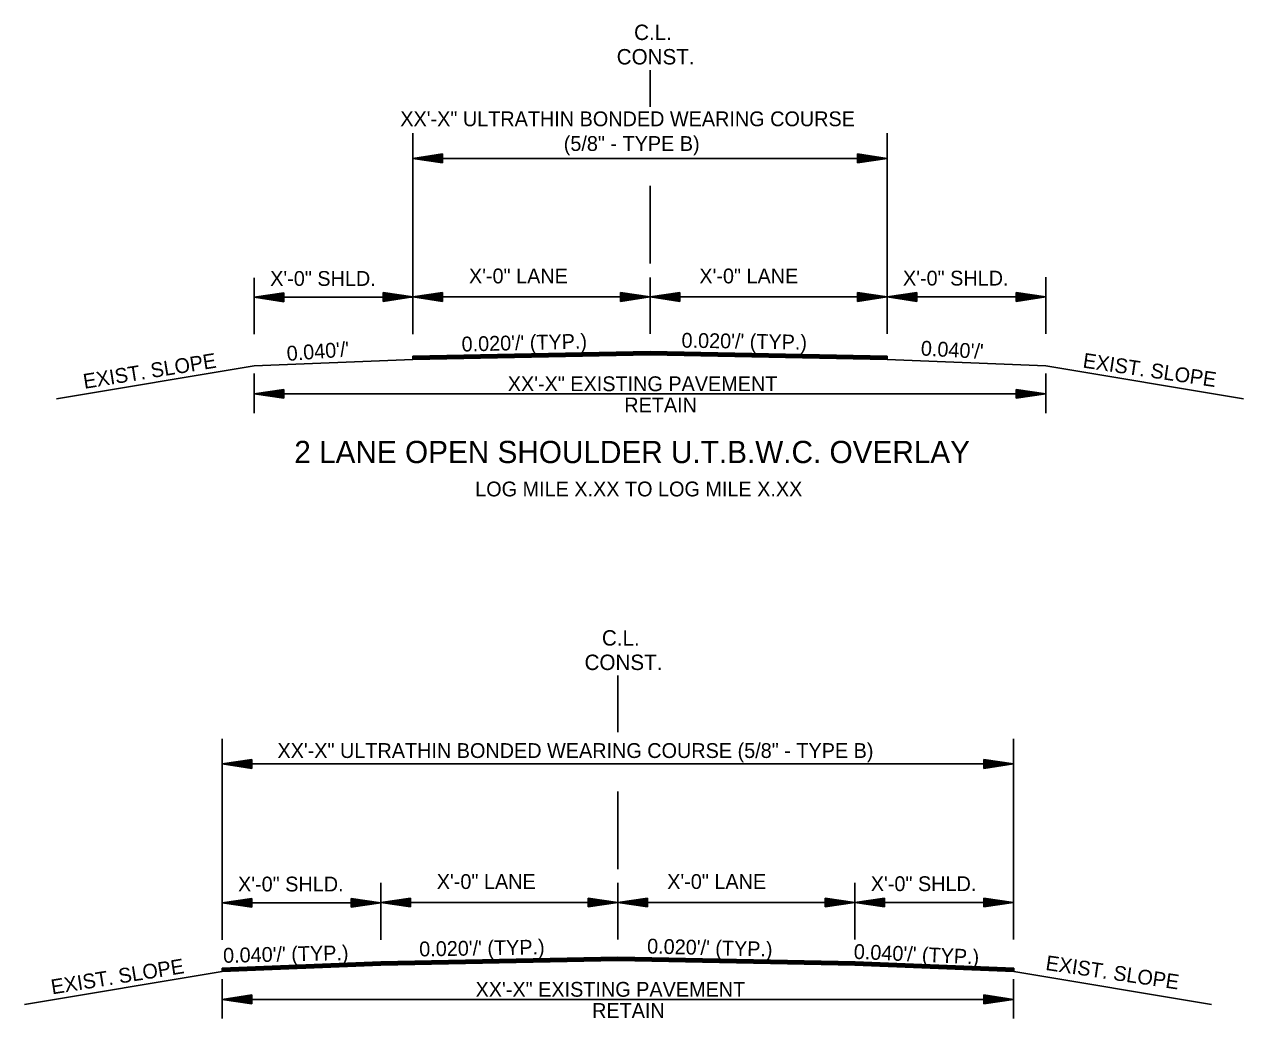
# Model space of a CAD drawing. Extents: x 542112 to 1930787, y -1968972 to 596640.
# Drawn here: x 546654 to 547271, y -1951932 to -1951428 of the extents above; entities that cross this region are included whole.
import ezdxf

# ---------------------------------------------------------------- set-up
doc = ezdxf.new("R2010")
doc.units = 0
doc.layers.add('Default', color=7, linetype='Continuous')
doc.layers.add('R_Draft', color=7, linetype='Continuous')

msp = doc.modelspace()

# ---------------------------------------------------------------- linework, layer by layer
at = {"layer": 'R_Draft'}
for p, q in [((546970.96, -1951470.01), (546970.96, -1951451.34)), ((546850.96, -1951483.29), (546850.96, -1951585.02)), ((546865.96, -1951493.8), (546850.96, -1951496.05)), ((546850.96, -1951496.05), (547090.89, -1951496.05)), ((546865.96, -1951498.3), (546850.96, -1951496.05)), ((546865.96, -1951494.18), (546853.46, -1951496.05)), ((546865.96, -1951497.93), (546853.46, -1951496.05)), ((546865.96, -1951494.56), (546856.04, -1951496.05)), ((546865.96, -1951497.54), (546856.04, -1951496.05)), ((546865.96, -1951494.93), (546858.54, -1951496.05)), ((546865.96, -1951497.17), (546858.54, -1951496.05)), ((546865.96, -1951495.32), (546861.08, -1951496.05)), ((546865.96, -1951496.78), (546861.08, -1951496.05)), ((546865.96, -1951495.7), (546863.59, -1951496.05)), ((546865.96, -1951496.4), (546863.59, -1951496.05)), ((546865.96, -1951498.3), (546865.96, -1951493.8)), ((547075.89, -1951493.8), (547090.89, -1951496.05)), ((547075.89, -1951493.8), (547075.89, -1951498.3)), ((547075.89, -1951494.18), (547088.38, -1951496.05)), ((547075.89, -1951494.56), (547085.8, -1951496.05)), ((547075.89, -1951494.93), (547083.3, -1951496.05)), ((547075.89, -1951495.32), (547080.76, -1951496.05)), ((547075.89, -1951495.7), (547078.26, -1951496.05)), ((547075.89, -1951498.3), (547090.89, -1951496.05)), ((547075.89, -1951496.79), (547080.76, -1951496.05)), ((547075.89, -1951497.54), (547085.8, -1951496.05)), ((547075.89, -1951497.93), (547088.38, -1951496.05)), ((547075.89, -1951497.17), (547083.3, -1951496.05)), ((547075.89, -1951496.4), (547078.26, -1951496.05)), ((546970.96, -1951549.29), (546970.96, -1951509.94)), ((546770.7, -1951585.02), (546770.7, -1951556.47)), ((546970.96, -1951584.85), (546970.96, -1951556.3)), ((547171.15, -1951584.85), (547171.15, -1951556.13)), ((546785.7, -1951564.11), (546770.7, -1951566.36)), ((546850.96, -1951566.36), (546770.7, -1951566.36)), ((546785.7, -1951568.61), (546770.7, -1951566.36)), ((546785.7, -1951564.49), (546773.2, -1951566.36)), ((546785.7, -1951568.24), (546773.2, -1951566.36)), ((546785.7, -1951564.87), (546775.78, -1951566.36)), ((546785.7, -1951567.86), (546775.78, -1951566.36)), ((546785.7, -1951565.25), (546778.28, -1951566.36)), ((546785.7, -1951567.48), (546778.28, -1951566.36)), ((546785.7, -1951565.63), (546780.82, -1951566.36)), ((546785.7, -1951567.09), (546780.82, -1951566.36)), ((546785.7, -1951566.01), (546783.33, -1951566.36)), ((546785.7, -1951566.72), (546783.33, -1951566.36)), ((546785.7, -1951568.61), (546785.7, -1951564.11)), ((546835.96, -1951563.94), (546850.96, -1951566.19)), ((546835.96, -1951563.94), (546835.96, -1951568.44)), ((546835.96, -1951564.32), (546848.45, -1951566.19)), ((546835.96, -1951564.7), (546845.87, -1951566.19)), ((546835.96, -1951565.08), (546843.38, -1951566.19)), ((546835.96, -1951565.47), (546840.83, -1951566.19)), ((546835.96, -1951565.84), (546838.33, -1951566.19)), ((546835.96, -1951568.44), (546850.96, -1951566.19)), ((546835.96, -1951566.93), (546840.83, -1951566.19)), ((546835.96, -1951567.69), (546845.87, -1951566.19)), ((546835.96, -1951568.07), (546848.45, -1951566.19)), ((546835.96, -1951567.31), (546843.38, -1951566.19)), ((546835.96, -1951566.55), (546838.33, -1951566.19)), ((546865.96, -1951563.94), (546850.96, -1951566.19)), ((546970.96, -1951566.19), (546850.96, -1951566.19)), ((546865.96, -1951568.44), (546850.96, -1951566.19)), ((546865.96, -1951564.32), (546853.46, -1951566.19)), ((546865.96, -1951568.07), (546853.46, -1951566.19)), ((546865.96, -1951564.7), (546856.04, -1951566.19)), ((546865.96, -1951567.69), (546856.04, -1951566.19)), ((546865.96, -1951565.08), (546858.54, -1951566.19)), ((546865.96, -1951567.31), (546858.54, -1951566.19)), ((546865.96, -1951565.46), (546861.08, -1951566.19)), ((546865.96, -1951566.92), (546861.08, -1951566.19)), ((546865.96, -1951565.84), (546863.59, -1951566.19)), ((546865.96, -1951566.55), (546863.59, -1951566.19)), ((546865.96, -1951568.44), (546865.96, -1951563.94)), ((546955.96, -1951563.94), (546970.96, -1951566.19)), ((546955.96, -1951563.94), (546955.96, -1951568.44)), ((546955.96, -1951564.32), (546968.45, -1951566.19)), ((546955.96, -1951564.7), (546965.87, -1951566.19)), ((546955.96, -1951565.08), (546963.38, -1951566.19)), ((546955.96, -1951565.47), (546960.83, -1951566.19)), ((546955.96, -1951565.84), (546958.33, -1951566.19)), ((546955.96, -1951568.44), (546970.96, -1951566.19)), ((546955.96, -1951566.93), (546960.83, -1951566.19)), ((546955.96, -1951567.69), (546965.87, -1951566.19)), ((546955.96, -1951568.07), (546968.45, -1951566.19)), ((546955.96, -1951567.31), (546963.38, -1951566.19)), ((546955.96, -1951566.55), (546958.33, -1951566.19)), ((546985.96, -1951563.94), (546970.96, -1951566.19)), ((547090.89, -1951566.19), (546970.96, -1951566.19)), ((546985.96, -1951568.44), (546970.96, -1951566.19)), ((546985.96, -1951564.32), (546973.46, -1951566.19)), ((546985.96, -1951568.07), (546973.46, -1951566.19)), ((546985.96, -1951564.7), (546976.04, -1951566.19)), ((546985.96, -1951567.69), (546976.04, -1951566.19)), ((546985.96, -1951565.08), (546978.54, -1951566.19)), ((546985.96, -1951567.31), (546978.54, -1951566.19)), ((546985.96, -1951565.46), (546981.08, -1951566.19)), ((546985.96, -1951566.92), (546981.08, -1951566.19)), ((546985.96, -1951565.84), (546983.59, -1951566.19)), ((546985.96, -1951566.55), (546983.59, -1951566.19)), ((546985.96, -1951568.44), (546985.96, -1951563.94)), ((547075.89, -1951563.94), (547090.89, -1951566.19)), ((547075.89, -1951563.94), (547075.89, -1951568.44)), ((547075.89, -1951564.32), (547088.38, -1951566.19)), ((547075.89, -1951564.7), (547085.8, -1951566.19)), ((547075.89, -1951565.08), (547083.3, -1951566.19)), ((547075.89, -1951565.47), (547080.76, -1951566.19)), ((547075.89, -1951565.84), (547078.26, -1951566.19)), ((547075.89, -1951568.44), (547090.89, -1951566.19)), ((547075.89, -1951566.93), (547080.76, -1951566.19)), ((547075.89, -1951567.69), (547085.8, -1951566.19)), ((547075.89, -1951568.07), (547088.38, -1951566.19)), ((547075.89, -1951567.31), (547083.3, -1951566.19)), ((547075.89, -1951566.55), (547078.26, -1951566.19)), ((547105.89, -1951563.94), (547090.89, -1951566.19)), ((547171.15, -1951566.19), (547090.89, -1951566.19)), ((547105.89, -1951568.44), (547090.89, -1951566.19)), ((547105.89, -1951564.32), (547093.39, -1951566.19)), ((547105.89, -1951568.07), (547093.39, -1951566.19)), ((547105.89, -1951564.7), (547095.97, -1951566.19)), ((547105.89, -1951567.69), (547095.97, -1951566.19)), ((547105.89, -1951565.08), (547098.47, -1951566.19)), ((547105.89, -1951567.31), (547098.47, -1951566.19)), ((547105.89, -1951565.46), (547101.01, -1951566.19)), ((547105.89, -1951566.92), (547101.01, -1951566.19)), ((547105.89, -1951565.84), (547103.52, -1951566.19)), ((547105.89, -1951566.55), (547103.52, -1951566.19)), ((547105.89, -1951568.44), (547105.89, -1951563.94)), ((547156.15, -1951563.94), (547171.15, -1951566.19)), ((547156.15, -1951563.94), (547156.15, -1951568.44)), ((547156.15, -1951564.32), (547168.64, -1951566.19)), ((547156.15, -1951564.7), (547166.06, -1951566.19)), ((547156.15, -1951565.08), (547163.56, -1951566.19)), ((547156.15, -1951565.47), (547161.02, -1951566.19)), ((547156.15, -1951565.84), (547158.52, -1951566.19)), ((547156.15, -1951568.44), (547171.15, -1951566.19)), ((547156.15, -1951566.93), (547161.02, -1951566.19)), ((547156.15, -1951567.69), (547166.06, -1951566.19)), ((547156.15, -1951568.07), (547168.64, -1951566.19)), ((547156.15, -1951567.31), (547163.56, -1951566.19)), ((547156.15, -1951566.55), (547158.52, -1951566.19)), ((546970.96, -1951593.8), (546850.96, -1951596.2)), ((546850.96, -1951596.2), (546850.99, -1951597.9)), ((546970.97, -1951594.1), (546850.97, -1951596.5)), ((546970.97, -1951594.4), (546850.97, -1951596.8)), ((546970.98, -1951594.7), (546850.98, -1951597.1)), ((546970.98, -1951595), (546850.98, -1951597.4)), ((546970.99, -1951595.3), (546850.99, -1951597.7)), ((546970.99, -1951595.5), (546850.99, -1951597.9)), ((546970.93, -1951595.3), (547090.93, -1951597.7)), ((546970.93, -1951595.5), (547090.93, -1951597.9)), ((546970.94, -1951594.7), (547090.94, -1951597.1)), ((546970.94, -1951595), (547090.94, -1951597.4)), ((546970.95, -1951594.1), (547090.95, -1951596.5)), ((546970.95, -1951594.4), (547090.95, -1951596.8)), ((546970.96, -1951593.8), (547090.96, -1951596.2)), ((547090.96, -1951596.2), (547090.93, -1951597.9)), ((546770.7, -1951601.11), (546670.63, -1951617.79)), ((546770.7, -1951601.11), (546850.99, -1951597.9)), ((547171.22, -1951601.11), (547090.93, -1951597.9)), ((547271.29, -1951617.79), (547171.22, -1951601.11)), ((546770.7, -1951604.97), (546770.7, -1951624.97)), ((547171.15, -1951604.97), (547171.15, -1951624.97)), ((546785.7, -1951612.97), (546770.7, -1951615.22)), ((546770.7, -1951615.22), (547171.15, -1951615.22)), ((546785.7, -1951617.47), (546770.7, -1951615.22)), ((546785.7, -1951613.34), (546773.2, -1951615.22)), ((546785.7, -1951617.09), (546773.2, -1951615.22)), ((546785.7, -1951613.72), (546775.78, -1951615.22)), ((546785.7, -1951616.71), (546775.78, -1951615.22)), ((546785.7, -1951614.1), (546778.28, -1951615.22)), ((546785.7, -1951616.33), (546778.28, -1951615.22)), ((546785.7, -1951614.48), (546780.82, -1951615.22)), ((546785.7, -1951615.94), (546780.82, -1951615.22)), ((546785.7, -1951614.86), (546783.33, -1951615.22)), ((546785.7, -1951615.57), (546783.33, -1951615.22)), ((546785.7, -1951617.47), (546785.7, -1951612.97)), ((547156.15, -1951612.97), (547171.15, -1951615.22)), ((547156.15, -1951612.97), (547156.15, -1951617.47)), ((547156.15, -1951613.34), (547168.64, -1951615.22)), ((547156.15, -1951613.72), (547166.06, -1951615.22)), ((547156.15, -1951614.1), (547163.56, -1951615.22)), ((547156.15, -1951614.49), (547161.02, -1951615.22)), ((547156.15, -1951614.86), (547158.52, -1951615.22)), ((547156.15, -1951617.47), (547171.15, -1951615.22)), ((547156.15, -1951615.95), (547161.02, -1951615.22)), ((547156.15, -1951616.71), (547166.06, -1951615.22)), ((547156.15, -1951617.09), (547168.64, -1951615.22)), ((547156.15, -1951616.33), (547163.56, -1951615.22)), ((547156.15, -1951615.57), (547158.52, -1951615.22)), ((546954.68, -1951786.52), (546954.68, -1951757.88)), ((546754.42, -1951789.83), (546754.42, -1951891.56)), ((546769.42, -1951800.34), (546754.42, -1951802.59)), ((546769.42, -1951800.72), (546756.93, -1951802.59)), ((546769.42, -1951801.1), (546759.51, -1951802.59)), ((546769.42, -1951804.84), (546769.42, -1951800.34)), ((547139.87, -1951800.34), (547154.87, -1951802.59)), ((547139.87, -1951800.34), (547139.87, -1951804.84)), ((547139.87, -1951800.72), (547152.36, -1951802.59)), ((547139.87, -1951801.1), (547149.78, -1951802.59)), ((546754.42, -1951802.59), (547154.87, -1951802.59)), ((546769.42, -1951804.84), (546754.42, -1951802.59)), ((546769.42, -1951804.47), (546756.93, -1951802.59)), ((546769.42, -1951804.08), (546759.51, -1951802.59)), ((546769.42, -1951801.47), (546762, -1951802.59)), ((546769.42, -1951803.71), (546762, -1951802.59)), ((546769.42, -1951801.86), (546764.55, -1951802.59)), ((546769.42, -1951803.32), (546764.55, -1951802.59)), ((546769.42, -1951802.24), (546767.05, -1951802.59)), ((546769.42, -1951802.94), (546767.05, -1951802.59)), ((547139.87, -1951801.47), (547147.29, -1951802.59)), ((547139.87, -1951801.86), (547144.74, -1951802.59)), ((547139.87, -1951802.24), (547142.24, -1951802.59)), ((547139.87, -1951804.84), (547154.87, -1951802.59)), ((547139.87, -1951803.33), (547144.74, -1951802.59)), ((547139.87, -1951804.08), (547149.78, -1951802.59)), ((547139.87, -1951804.47), (547152.36, -1951802.59)), ((547139.87, -1951803.71), (547147.29, -1951802.59)), ((547139.87, -1951802.94), (547142.24, -1951802.59)), ((546954.68, -1951855.83), (546954.68, -1951816.48)), ((546834.68, -1951891.39), (546834.68, -1951862.84)), ((546834.68, -1951891.56), (546834.68, -1951862.84)), ((546954.68, -1951891.39), (546954.68, -1951862.84)), ((547074.61, -1951872.73), (547074.61, -1951862.84)), ((547074.61, -1951891.39), (547074.61, -1951862.84)), ((546769.42, -1951870.65), (546754.42, -1951872.9)), ((546834.68, -1951872.9), (546754.42, -1951872.9)), ((546769.42, -1951875.15), (546754.42, -1951872.9)), ((546769.42, -1951871.03), (546756.93, -1951872.9)), ((546769.42, -1951874.78), (546756.93, -1951872.9)), ((546769.42, -1951871.41), (546759.51, -1951872.9)), ((546769.42, -1951874.4), (546759.51, -1951872.9)), ((546769.42, -1951871.79), (546762, -1951872.9)), ((546769.42, -1951874.02), (546762, -1951872.9)), ((546769.42, -1951872.17), (546764.55, -1951872.9)), ((546769.42, -1951873.63), (546764.55, -1951872.9)), ((546769.42, -1951872.55), (546767.05, -1951872.9)), ((546769.42, -1951873.26), (546767.05, -1951872.9)), ((546769.42, -1951875.15), (546769.42, -1951870.65)), ((546819.68, -1951870.65), (546834.68, -1951872.9)), ((546819.68, -1951870.65), (546819.68, -1951875.15)), ((546819.68, -1951871.03), (546832.18, -1951872.9)), ((546819.68, -1951871.41), (546829.6, -1951872.9)), ((546819.68, -1951871.79), (546827.1, -1951872.9)), ((546819.68, -1951872.18), (546824.56, -1951872.9)), ((546819.68, -1951872.55), (546822.05, -1951872.9)), ((546819.68, -1951875.15), (546834.68, -1951872.9)), ((546819.68, -1951873.64), (546824.56, -1951872.9)), ((546819.68, -1951874.4), (546829.6, -1951872.9)), ((546819.68, -1951874.78), (546832.18, -1951872.9)), ((546819.68, -1951874.02), (546827.1, -1951872.9)), ((546819.68, -1951873.26), (546822.05, -1951872.9)), ((546849.68, -1951870.48), (546834.68, -1951872.73)), ((546954.68, -1951872.73), (546834.68, -1951872.73)), ((546849.68, -1951874.98), (546834.68, -1951872.73)), ((546849.68, -1951870.86), (546837.19, -1951872.73)), ((546849.68, -1951874.61), (546837.19, -1951872.73)), ((546849.68, -1951871.24), (546839.77, -1951872.73)), ((546849.68, -1951874.23), (546839.77, -1951872.73)), ((546849.68, -1951871.62), (546842.26, -1951872.73)), ((546849.68, -1951873.85), (546842.26, -1951872.73)), ((546849.68, -1951872), (546844.81, -1951872.73)), ((546849.68, -1951873.46), (546844.81, -1951872.73)), ((546849.68, -1951872.38), (546847.31, -1951872.73)), ((546849.68, -1951873.09), (546847.31, -1951872.73)), ((546849.68, -1951874.98), (546849.68, -1951870.48)), ((546939.68, -1951870.48), (546954.68, -1951872.73)), ((546939.68, -1951870.48), (546939.68, -1951874.98)), ((546939.68, -1951870.86), (546952.18, -1951872.73)), ((546939.68, -1951871.24), (546949.6, -1951872.73)), ((546939.68, -1951871.62), (546947.1, -1951872.73)), ((546939.68, -1951872.01), (546944.56, -1951872.73)), ((546939.68, -1951872.38), (546942.05, -1951872.73)), ((546939.68, -1951874.98), (546954.68, -1951872.73)), ((546939.68, -1951873.47), (546944.56, -1951872.73)), ((546939.68, -1951874.23), (546949.6, -1951872.73)), ((546939.68, -1951874.61), (546952.18, -1951872.73)), ((546939.68, -1951873.85), (546947.1, -1951872.73)), ((546939.68, -1951873.09), (546942.05, -1951872.73)), ((546969.68, -1951870.48), (546954.68, -1951872.73)), ((547074.61, -1951872.73), (546954.68, -1951872.73)), ((546969.68, -1951874.98), (546954.68, -1951872.73)), ((546969.68, -1951870.86), (546957.19, -1951872.73)), ((546969.68, -1951874.61), (546957.19, -1951872.73)), ((546969.68, -1951871.24), (546959.77, -1951872.73)), ((546969.68, -1951874.23), (546959.77, -1951872.73)), ((546969.68, -1951871.62), (546962.26, -1951872.73)), ((546969.68, -1951873.85), (546962.26, -1951872.73)), ((546969.68, -1951872), (546964.81, -1951872.73)), ((546969.68, -1951873.46), (546964.81, -1951872.73)), ((546969.68, -1951872.38), (546967.31, -1951872.73)), ((546969.68, -1951873.09), (546967.31, -1951872.73)), ((546969.68, -1951874.98), (546969.68, -1951870.48)), ((547059.61, -1951870.48), (547074.61, -1951872.73)), ((547059.61, -1951870.48), (547059.61, -1951874.98)), ((547059.61, -1951870.86), (547072.1, -1951872.73)), ((547059.61, -1951871.24), (547069.52, -1951872.73)), ((547059.61, -1951871.62), (547067.03, -1951872.73)), ((547059.61, -1951872.01), (547064.48, -1951872.73)), ((547059.61, -1951872.38), (547061.98, -1951872.73)), ((547059.61, -1951874.98), (547074.61, -1951872.73)), ((547059.61, -1951873.47), (547064.48, -1951872.73)), ((547059.61, -1951874.23), (547069.52, -1951872.73)), ((547059.61, -1951874.61), (547072.1, -1951872.73)), ((547059.61, -1951873.85), (547067.03, -1951872.73)), ((547059.61, -1951873.09), (547061.98, -1951872.73)), ((547089.61, -1951870.48), (547074.61, -1951872.73)), ((547074.61, -1951891.39), (547074.61, -1951872.73)), ((547154.87, -1951872.73), (547074.61, -1951872.73)), ((547089.61, -1951874.98), (547074.61, -1951872.73)), ((547089.61, -1951870.86), (547077.11, -1951872.73)), ((547089.61, -1951874.61), (547077.11, -1951872.73)), ((547089.61, -1951871.24), (547079.69, -1951872.73)), ((547089.61, -1951874.23), (547079.69, -1951872.73)), ((547089.61, -1951871.62), (547082.19, -1951872.73)), ((547089.61, -1951873.85), (547082.19, -1951872.73)), ((547089.61, -1951872), (547084.73, -1951872.73)), ((547089.61, -1951873.46), (547084.73, -1951872.73)), ((547089.61, -1951872.38), (547087.24, -1951872.73)), ((547089.61, -1951873.09), (547087.24, -1951872.73)), ((547089.61, -1951874.98), (547089.61, -1951870.48)), ((547139.87, -1951870.48), (547154.87, -1951872.73)), ((547139.87, -1951870.48), (547139.87, -1951874.98)), ((547139.87, -1951870.86), (547152.36, -1951872.73)), ((547139.87, -1951871.24), (547149.78, -1951872.73)), ((547139.87, -1951871.62), (547147.29, -1951872.73)), ((547139.87, -1951872.01), (547144.74, -1951872.73)), ((547139.87, -1951872.38), (547142.24, -1951872.73)), ((547139.87, -1951874.98), (547154.87, -1951872.73)), ((547139.87, -1951873.47), (547144.74, -1951872.73)), ((547139.87, -1951874.23), (547149.78, -1951872.73)), ((547139.87, -1951874.61), (547152.36, -1951872.73)), ((547139.87, -1951873.85), (547147.29, -1951872.73)), ((547139.87, -1951873.09), (547142.24, -1951872.73)), ((546754.42, -1951905.95), (546834.68, -1951902.74)), ((546754.42, -1951906.25), (546834.69, -1951903.04)), ((546754.42, -1951906.55), (546834.71, -1951903.34)), ((546754.42, -1951906.85), (546834.72, -1951903.64)), ((546754.42, -1951907.15), (546834.73, -1951903.94)), ((546754.42, -1951907.45), (546834.74, -1951904.24)), ((546754.42, -1951907.65), (546834.75, -1951904.44)), ((546754.42, -1951907.65), (546754.42, -1951905.95)), ((546954.68, -1951900.34), (546834.68, -1951902.74)), ((546954.69, -1951900.64), (546834.69, -1951903.04)), ((546954.69, -1951900.94), (546834.69, -1951903.34)), ((546954.7, -1951901.24), (546834.7, -1951903.64)), ((546954.71, -1951901.54), (546834.71, -1951903.94)), ((546954.71, -1951901.84), (546834.71, -1951904.24)), ((546954.72, -1951902.04), (546834.72, -1951904.44)), ((546954.65, -1951901.84), (547074.65, -1951904.24)), ((546954.65, -1951902.04), (547074.65, -1951904.44)), ((546954.66, -1951901.24), (547074.66, -1951903.64)), ((546954.66, -1951901.54), (547074.66, -1951903.94)), ((546954.67, -1951900.94), (547074.67, -1951903.34)), ((546954.68, -1951900.34), (547074.68, -1951902.74)), ((546954.68, -1951900.64), (547074.68, -1951903.04)), ((547154.94, -1951907.65), (547074.61, -1951904.44)), ((547154.94, -1951907.45), (547074.62, -1951904.24)), ((547154.94, -1951907.15), (547074.63, -1951903.94)), ((547154.94, -1951906.85), (547074.65, -1951903.64)), ((547154.94, -1951906.55), (547074.66, -1951903.34)), ((547154.94, -1951906.25), (547074.67, -1951903.04)), ((547154.94, -1951905.95), (547074.68, -1951902.74)), ((547154.94, -1951907.65), (547154.94, -1951905.95)), ((546754.42, -1951907.65), (546654.35, -1951924.33)), ((546754.42, -1951911.51), (546754.42, -1951931.51)), ((547154.87, -1951911.51), (547154.87, -1951931.51)), ((547255.01, -1951924.33), (547154.94, -1951907.65)), ((546769.42, -1951919.5), (546754.42, -1951921.75)), ((546754.42, -1951921.75), (547154.87, -1951921.75)), ((546769.42, -1951924), (546754.42, -1951921.75)), ((546769.42, -1951919.88), (546756.93, -1951921.75)), ((546769.42, -1951923.63), (546756.93, -1951921.75)), ((546769.42, -1951920.26), (546759.51, -1951921.75)), ((546769.42, -1951923.25), (546759.51, -1951921.75)), ((546769.42, -1951920.64), (546762, -1951921.75)), ((546769.42, -1951922.87), (546762, -1951921.75)), ((546769.42, -1951921.02), (546764.55, -1951921.75)), ((546769.42, -1951922.48), (546764.55, -1951921.75)), ((546769.42, -1951921.4), (546767.05, -1951921.75)), ((546769.42, -1951922.11), (546767.05, -1951921.75)), ((546769.42, -1951924), (546769.42, -1951919.5)), ((547139.87, -1951919.5), (547154.87, -1951921.75)), ((547139.87, -1951919.5), (547139.87, -1951924)), ((547139.87, -1951919.88), (547152.36, -1951921.75)), ((547139.87, -1951920.26), (547149.78, -1951921.75)), ((547139.87, -1951920.64), (547147.29, -1951921.75)), ((547139.87, -1951921.03), (547144.74, -1951921.75)), ((547139.87, -1951921.4), (547142.24, -1951921.75)), ((547139.87, -1951924), (547154.87, -1951921.75)), ((547139.87, -1951922.49), (547144.74, -1951921.75)), ((547139.87, -1951923.25), (547149.78, -1951921.75)), ((547139.87, -1951923.63), (547152.36, -1951921.75)), ((547139.87, -1951922.87), (547147.29, -1951921.75)), ((547139.87, -1951922.11), (547142.24, -1951921.75))]:
    msp.add_line(p, q, dxfattribs=at)
for points in [[(547090.89, -1951483.29), (547090.89, -1951584.85)], [(547154.87, -1951789.83), (547154.87, -1951891.39)]]:
    msp.add_lwpolyline(points, dxfattribs=at)

# ---------------------------------------------------------------- texts
at = {"layer": 'Default'}
for s, p in [('XX\'-X" EXISTING PAVEMENT', (546898.94, -1951613.89)), ('RETAIN', (546957.88, -1951624.62)), ('XX\'-X" EXISTING PAVEMENT', (546882.66, -1951920.43)), ('RETAIN', (546941.6, -1951931.15))]:
    msp.add_text(s, height=7.5, dxfattribs=at).set_placement(p)
at = {"layer": 'R_Draft'}
for s, height, p in [('C.L.', 7.8, (546962.86, -1951436.14)), ('CONST.', 7.8, (546954.07, -1951448.51)), ('XX\'-X" ULTRATHIN BONDED WEARING COURSE', 7.5, (546844.57, -1951479.78)), ('(5/8" - TYPE B)', 7.5, (546927.27, -1951492.29)), ('X\'-0" SHLD.', 7.5, (546778.73, -1951560.59)), ('X\'-0" LANE', 7.5, (546879.3, -1951559.33)), ('X\'-0" LANE', 7.5, (546995.89, -1951559.33)), ('X\'-0" SHLD.', 7.5, (547098.92, -1951560.42)), ('2 LANE OPEN SHOULDER U.T.B.W.C. OVERLAY', 11.25, (546790.92, -1951650.3)), ('LOG MILE X.XX TO LOG MILE X.XX', 7.5, (546882.46, -1951667.16)), ('C.L.', 7.8, (546946.58, -1951742.68)), ('CONST.', 7.8, (546937.8, -1951755.05)), ('XX\'-X" ULTRATHIN BONDED WEARING COURSE (5/8" - TYPE B)', 7.5, (546782.4, -1951799.57)), ('X\'-0" SHLD.', 7.5, (546762.46, -1951867.13)), ('X\'-0" LANE', 7.5, (546863.02, -1951865.87)), ('X\'-0" LANE', 7.5, (546979.62, -1951865.87)), ('X\'-0" SHLD.', 7.5, (547082.64, -1951866.96))]:
    msp.add_text(s, height=height, dxfattribs=at).set_placement(p)
for s, rotation, p in [("0.020'/' (TYP.)", 1.42536, (546875.67, -1951593.85)), ("0.020'/' (TYP.)", 359.06285, (546986.83, -1951591.84)), ("0.040'/'", 4.25245, (546787.36, -1951598.6)), ("0.040'/'", 356.79663, (547107.81, -1951595.8)), ('EXIST. SLOPE', 9.15344, (546684.74, -1951612.73)), ('EXIST. SLOPE', 351.57554, (547189.59, -1951601.9)), ("0.020'/' (TYP.)", 0.97192, (546854.2, -1951900.03)), ("0.020'/' (TYP.)", 358.5057, (546969.38, -1951898.5)), ("0.040'/' (TYP.)", 357.39273, (547073.9, -1951901.22)), ("0.040'/' (TYP.)", 1.31838, (546754.98, -1951903.28)), ('EXIST. SLOPE', 351.57554, (547170.77, -1951906.82)), ('EXIST. SLOPE', 9.15344, (546668.46, -1951919.26))]:
    msp.add_text(s, height=7.5, rotation=rotation, dxfattribs=at).set_placement(p)

doc.saveas('drawing.dxf')
